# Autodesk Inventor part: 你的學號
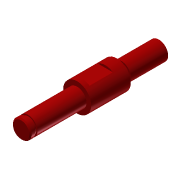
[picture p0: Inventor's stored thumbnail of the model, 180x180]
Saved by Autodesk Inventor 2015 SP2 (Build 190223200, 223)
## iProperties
Created: 2006-03
Part Number: 你的學號
Document SubType Name: Modeling
Density: 1 g/cm^3
Material: 一般
Appearance: Smooth - Red
Author: 你的姓名
Title: 中斷與局部放大
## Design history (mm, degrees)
sketch "草圖1"
  geometry: L1 (0, 38)-(0, -38); L2 (0, 37)-(-4, 37); L3 (-4, 37)-(-4, 21); L4 (-4, 21)-(-3.317, 21); L5 (-3.317, 21)-(-3.317, 19); L6 (-3.317, 19)-(-6, 19); L7 (-6, 19)-(-6, 2); L8 (-6, 2)-(-4, 2); L9 (-4, 2)-(-4, -19); L10 (-4, -19)-(-3.5, -19); L11 (-3.5, -19)-(-3.5, -19.9); L12 (-3.5, -19.9)-(-4, -19.9); L13 (-4, -19.9)-(-4, -22); L14 (-4, -22)-(0, -22); L15 (-3.317, 52.234)-(3.317, 52.234); L16 (3.317, 42.234)-(-3.317, 42.234); A1 r 6 centre (0, 47.234) between (3.317, 52.234) and (3.317, 42.234); 3 further points
  constraints: 32 end point, 10 parallel, 5 perpendicular, 4 point on circle, 2 midpoint, 2 point on line, 2 vertical alignment, 1 centre point, 1 coincident, 1 collinear, 1 vertical
  dimensions: "d0" = 8 diameter of L3 L1; "d1" = 16 distance of L2.end L3.end; "d2" = 2 distance of L4.end L5.end; "d3" = 12 diameter of L7 L1; "d4" = 8 diameter of L9 L1; "d5" = 7 diameter of L11 L1; "d6" = 0.9 distance of L10.end L11.end; "d7" = 2.1 distance of L12.end L13.end; "d8" = 21 distance of L8.end L9.end; "d9" = 8 diameter of L13 L1; "d10" = 24 distance between parallel lines of L14 L8 (derived); "d11" = 59 distance between parallel lines of L2 L14; "d12" = 17 distance of L6.end L7.end (derived); "d14" = 12 diameter of A1; "d15" = 10 distance between parallel lines of L16 L15
revolve "迴轉1" sketch "草圖1" stored, may be unused: angle "d16" = 90 deg
node "工作平面1"
sketch "草圖2"
  geometry: L1 (-3.317, 5)-(3.317, 5); L2 (3.317, -5)-(-3.317, -5); A1 r 6 centre (0, 0) between (-3.317, 5) and (3.317, 5) reference
  constraints: 4 end point, 4 point on circle, 2 parallel
  dimensions: "d18" = 10 distance between parallel lines of L2 L1
extrude "擠出1" cut sketch "草圖2" distance "d19" = 10; taper "d20" = 0 deg
chamfer "去角1" distance "d21" = 0.5; stored, may be unused: second distance "d22" = 2, angle "d23" = 45 deg
node "實體1"
node "實體本體"
node "曲面本體"
other parameters: "A1" = 1 [user parameter], "d17" = -2
